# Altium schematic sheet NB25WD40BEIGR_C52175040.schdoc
size 127 x 101 mm
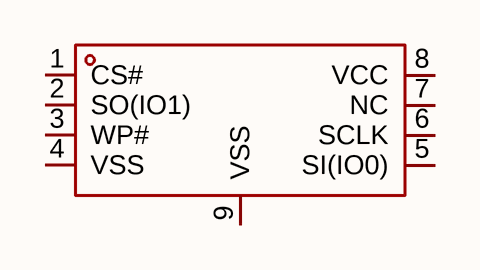
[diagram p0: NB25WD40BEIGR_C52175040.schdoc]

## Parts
U?  nb25wd40beigr_c52175040  [USON-8_L3.0-W2.0-P0.50-BL-EP_WINBOND_UX]  (value not drawn)

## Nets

Not connected (* = marked no-connect by the designer): U? 1(CS#) 2(SO(IO1)) 3(WP#) 4(VSS) 5(SI(IO0)) 6(SCLK) 7(NC) 8(VCC) 9(VSS)

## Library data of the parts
U? = nb25wd40beigr_c52175040: 接口类型:SPI;存储容量:4Mbit;时钟频率(fc):104MHz;; Manufacturer: Zetta(澜智); AddInBom: yes; ModelId: 12a239e5c7384371915ecb51201bf581; ModelName: USON-8_L3.0-W2.0-H0.6-P0.50; ModelTransform: 118.8974,78.74,0,90,0,0,0,0,0; Interface: SPI; Memory Size: 4Mbit; Clock Frequency: 104MHz; Voltage - Supply: 1.65V~3.6V; Standby Supply Current: 0.2uA; Program / Erase Cycles: 100000次; Page Programming Time (Tpp): 2ms; Block Erase Time(tBE): 10ms@(64KB); Data Retention - TDR (Year): 20年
